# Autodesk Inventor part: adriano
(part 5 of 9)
sketch "スケッチ139"
  geometry: L1 (17.25, -13.45)-(17.25, -5.9) reference; L2 (4.25, -13.4)-(4.25, -5.9) reference; L3 (4.25, -5.9)-(8.25, -5.9) reference; L4 (8.25, -5.9)-(8.25, -13.4) reference; L5 (8.25, -13.4)-(4.25, -13.4) reference; L6 (10.75, -13.45)-(10.75, -5.9) reference; L7 (23.75, -13.45)-(23.75, -5.9) reference; L8 (31.5, -17.464)-(31.5, -1.6) reference; L9 (4.25, -6.4)-(3.75, -6.4); L10 (3.75, -6.4)-(3.75, -5.4); L11 (3.75, -5.4)-(8.75, -5.4); L12 (8.75, -5.4)-(8.75, -6.4); L13 (8.75, -6.4)-(8.25, -6.4); L14 (8.25, -6.4)-(8.25, -5.9); L15 (8.25, -5.9)-(4.25, -5.9); L16 (4.25, -5.9)-(4.25, -6.4); L17 (15.25, -5.4)-(15.25, -6.4); L18 (14.75, -6.4)-(14.75, -5.9); L19 (15.25, -6.4)-(14.75, -6.4); L20 (10.75, -5.9)-(10.75, -6.4); L21 (10.75, -5.9)-(14.75, -5.9); L22 (14.75, -5.9)-(10.75, -5.9); L23 (10.75, -6.4)-(10.25, -6.4); L24 (10.25, -6.4)-(10.25, -5.4); L25 (10.25, -5.4)-(15.25, -5.4); L26 (17.25, -5.9)-(17.25, -6.4); L27 (16.75, -6.4)-(16.75, -5.4); L28 (21.75, -6.4)-(21.25, -6.4); L29 (21.25, -6.4)-(21.25, -5.9); L30 (21.25, -5.9)-(17.25, -5.9); L31 (16.75, -5.4)-(21.75, -5.4); L32 (21.75, -5.4)-(21.75, -6.4); L33 (17.25, -6.4)-(16.75, -6.4); L34 (17.25, -5.9)-(21.25, -5.9); L35 (23.75, -6.4)-(23.25, -6.4); L36 (23.75, -5.9)-(23.75, -6.4); L37 (23.25, -6.4)-(23.25, -5.4); L38 (23.75, -5.9)-(27.75, -5.9); L39 (28.25, -6.4)-(27.75, -6.4); L40 (23.25, -5.4)-(28.25, -5.4); L41 (28.25, -5.4)-(28.25, -6.4); L42 (27.75, -6.4)-(27.75, -5.9); L43 (27.75, -5.9)-(23.75, -5.9); L44 (3.75, -10.9)-(8.75, -10.9); L45 (8.75, -10.9)-(8.75, -13.9); L46 (8.75, -13.9)-(3.75, -13.9); L47 (3.75, -13.9)-(3.75, -10.9); L48 (10.25, -10.9)-(15.25, -10.9); L49 (15.25, -10.9)-(15.25, -13.9); L50 (15.25, -13.9)-(10.25, -13.9); L51 (10.25, -13.9)-(10.25, -10.9); L52 (16.75, -10.9)-(21.75, -10.9); L53 (21.75, -10.9)-(21.75, -13.9); L54 (21.75, -13.9)-(16.75, -13.9); L55 (16.75, -13.9)-(16.75, -10.9); L56 (23.25, -10.9)-(28.25, -10.9); L57 (28.25, -10.9)-(28.25, -13.9); L58 (28.25, -13.9)-(23.25, -13.9); L59 (23.25, -13.9)-(23.25, -10.9); L60 (3.75, -28.5)-(8.75, -28.5); L61 (8.75, -28.5)-(8.75, -31.5); L62 (8.75, -31.5)-(3.75, -31.5); L63 (3.75, -31.5)-(3.75, -28.5); L64 (10.25, -28.5)-(15.25, -28.5)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; A1 r 2.499 centre (6.25, -23.5) between (8.749, -23.5) and (3.751, -23.5); A2 r 1.999 centre (6.25, -23.5) between (8.249, -23.5) and (4.251, -23.5); A3 r 2.49 centre (12.75, -23.5) between (15.24, -23.5) and (10.26, -23.5); A4 r 1.99 centre (12.75, -23.5) between (14.74, -23.5) and (10.76, -23.5); A5 r 2.492 centre (19.25, -23.5) between (21.742, -23.5) and (16.758, -23.5); A6 r 1.992 centre (19.25, -23.5) between (21.242, -23.5) and (17.258, -23.5); A7 r 2.5 centre (25.75, -23.5) between (28.25, -23.5) and (23.25, -23.5); A8 r 2 centre (25.75, -23.5) between (27.75, -23.5) and (23.75, -23.5); 1 further point
  constraints: 150 end point, 25 parallel, 19 perpendicular, 16 point on circle, 8 centre point, 8 horizontal, 7 collinear, 4 coincident, 2 point on line
  dimensions: "d2453" = 0.5 distance of L9.start L9.end; "d2455" = 0.5 distance of L12.end L13.end; "d2456" = 0.5 distance between parallel lines of L11 L3; "d2457" = 1 distance of L9.end L10.end; "d2458" = 0 distance from line of L13.end L9; "d2459" = 0.5 distance of L20.end L23.end; "d2460" = 0.5 distance of L17.end L18.start; "d2461" = 0.5 distance between parallel lines of L25 L21; "d2462" = 1 distance of L23.end L24.end; "d2463" = 0 distance from line of L18.start L23; "d2464" = 0.5 distance of L26.end L27.start; "d2465" = 0.5 distance of L28.start L28.end; "d2466" = 0.5 distance between parallel lines of L31 L34; "d2467" = 1 distance of L27.start L27.end; "d2468" = 0 distance from line of L28.end L33; "d2469" = 0.5 distance of L35.start L35.end; "d2470" = 0.5 distance of L39.start L39.end; "d2471" = 0.5 distance between parallel lines of L40 L38; "d2472" = 1 distance of L35.end L37.end; "d2473" = 0 distance from line of L39.end L35; "d2474" = 0 distance between parallel lines of L25 L11; "d2475" = 0 distance between parallel lines of L31 L25; "d2476" = 0 distance between parallel lines of L40 L31; "d2477" = 0 distance between parallel lines of L6 L20; "d2478" = 0 distance between parallel lines of L1 L26; "d2479" = 0 distance between parallel lines of L7 L36; "d2480" = 0.5 distance between parallel lines of L5 L46; "d2481" = 0 distance between parallel lines of L50 L46; "d2482" = 0 distance between parallel lines of L54 L50; "d2483" = 0 distance between parallel lines of L58 L54; "d2484" = 0 distance between parallel lines of L52 L56; "d2485" = 3 distance of L46.end L44.start; "d2486" = 0 distance between parallel lines of L48 L44; "d2487" = 0 distance between parallel lines of L52 L48; "d2488" = 3 distance of L62.end L60.start; "d2489" = 0 distance between parallel lines of L64 L60; "d2490" = 0 distance between parallel lines of L68 L64; "d2491" = 0 distance between parallel lines of L72 L68; "d2492" = 0 distance between parallel lines of L66 L62; "d2493" = 0 distance between parallel lines of L70 L66; "d2494" = 0 distance between parallel lines of L74 L70; "d2495" = 0.5 distance between parallel lines of L62 L76; "d2496" = 0.5 distance of L77.start L77.end; "d2497" = 0.5 distance of L79.start L79.end; "d2498" = 0.5 distance of L82.start L82.end; "d2499" = 0.5 distance of L83.start L83.end; "d2500" = 0 vertical distance of A3.centre A1.centre; "d2501" = 0 vertical distance of A5.centre A3.centre; "d2502" = 0 vertical distance of A7.centre A5.centre; "d2503" = 0 vertical distance of L80.end L81.start; "d2504" = 0 distance between parallel lines of L79 L80; "d2505" = 0 distance from line of A3.centre L79; "d2506" = 0 distance between parallel lines of L79 L78; "d2507" = 5 distance from line of L60 A1.centre; "d2508" = 0 distance between parallel lines of L82 L77; "d2509" = 0 distance between parallel lines of L78 L77
extrude "押し出し129" join sketch "スケッチ139" distance "d2510" = 0.5; taper "d2511" = 0 deg
sketch "スケッチ141"
  geometry: L1 (-14.75, 20.4)-(-14.75, 27.9) reference; L2 (-14.75, 27.9)-(-10.75, 27.9) reference; L3 (-21.25, 20.4)-(-21.25, 27.9) reference; L4 (-21.25, 27.9)-(-17.25, 27.9) reference; L5 (-17.25, 27.9)-(-17.25, 20.4) reference; L6 (-8.25, 20.4)-(-8.25, 27.9) reference; L7 (-8.25, 27.9)-(-4.25, 27.9) reference; L8 (-0.5, 16.536)-(-25.5, 16.536) reference; L9 (-21.25, 27.4)-(-21.75, 27.4); L10 (-21.75, 27.4)-(-21.75, 28.4); L11 (-21.75, 28.4)-(-16.75, 28.4); L12 (-16.75, 28.4)-(-16.75, 27.4); L13 (-16.75, 27.4)-(-17.25, 27.4); L14 (-17.25, 27.4)-(-17.25, 27.9); L15 (-17.25, 27.9)-(-21.25, 27.9); L16 (-21.25, 27.9)-(-21.25, 27.4); L17 (-15.25, 27.4)-(-15.25, 28.4); L18 (-14.75, 27.4)-(-15.25, 27.4); L19 (-14.75, 27.9)-(-14.75, 27.4); L20 (-10.25, 27.4)-(-10.75, 27.4); L21 (-10.75, 27.4)-(-10.75, 27.9); L22 (-14.75, 27.9)-(-10.75, 27.9); L23 (-10.25, 28.4)-(-10.25, 27.4); L24 (-15.25, 28.4)-(-10.25, 28.4); L25 (-10.75, 27.9)-(-14.75, 27.9); L26 (-8.25, 27.4)-(-8.75, 27.4); L27 (-3.75, 27.4)-(-4.25, 27.4); L28 (-8.25, 27.9)-(-8.25, 27.4); L29 (-4.25, 27.4)-(-4.25, 27.9); L30 (-4.25, 27.9)-(-8.25, 27.9); L31 (-8.75, 27.4)-(-8.75, 28.4); L32 (-8.75, 28.4)-(-3.75, 28.4); L33 (-3.75, 28.4)-(-3.75, 27.4); L34 (-8.25, 27.9)-(-4.25, 27.9); L35 (-21.75, 23.001)-(-16.75, 23.001); L36 (-16.75, 23.001)-(-16.75, 20.001); L37 (-16.75, 20.001)-(-21.75, 20.001); L38 (-21.75, 20.001)-(-21.75, 23.001); L39 (-15.25, 23.001)-(-10.25, 23.001); L40 (-10.25, 23.001)-(-10.25, 20.001); L41 (-10.25, 20.001)-(-15.25, 20.001); L42 (-15.25, 20.001)-(-15.25, 23.001); L43 (-8.75, 23.001)-(-3.75, 23.001); L44 (-3.75, 23.001)-(-3.75, 20.001); L45 (-3.75, 20.001)-(-8.75, 20.001); L46 (-8.75, 20.001)-(-8.75, 23.001); L47 (-21.75, 5.5)-(-16.75, 5.5); L48 (-16.75, 5.5)-(-16.75, 2.5); L49 (-16.75, 2.5)-(-21.75, 2.5); L50 (-21.75, 2.5)-(-21.75, 5.5); L51 (-15.25, 5.5)-(-10.25, 5.5); L52 (-10.25, 5.5)-(-10.25, 2.5); L53 (-10.25, 2.5)-(-15.25, 2.5); L54 (-15.25, 2.5)-(-15.25, 5.5); L55 (-8.75, 5.5)-(-3.75, 5.5); L56 (-3.75, 5.5)-(-3.75, 2.5); L57 (-3.75, 2.5)-(-8.75, 2.5); L58 (-8.75, 2.5)-(-8.75, 5.5); L59 (-17.25, 3)-(-21.25, 3) reference; L60 (-14.75, 3)-(-14.75, 10.5) reference; L61 (-8.25, 3)-(-8.25, 10.5) reference; L62 (-21.75, 10.5)-(-21.25, 10.5); L63 (-17.25, 10.5)-(-16.75, 10.5); L64 (-15.25, 10.5)-(-14.75, 10.5)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; A1 r 2.5 centre (-19.25, 10.5) between (-16.75, 10.5) and (-21.75, 10.5); A2 r 2 centre (-19.25, 10.5) between (-17.25, 10.5) and (-21.25, 10.5); A3 r 2.5 centre (-12.75, 10.5) between (-10.25, 10.5) and (-15.25, 10.5); A4 r 2 centre (-12.75, 10.5) between (-10.75, 10.5) and (-14.75, 10.5); A5 r 2.5 centre (-6.25, 10.5) between (-3.75, 10.5) and (-8.75, 10.5); A6 r 2 centre (-6.25, 10.5) between (-4.25, 10.5) and (-8.25, 10.5); 2 further points
  constraints: 112 end point, 19 parallel, 14 perpendicular, 12 point on circle, 7 collinear, 6 centre point, 6 horizontal, 3 coincident, 2 point on line
  dimensions: "d2544" = 0.5 distance of L9.start L9.end; "d2546" = 0.5 distance of L12.end L13.end; "d2547" = 0.5 distance between parallel lines of L4 L11; "d2548" = 1 distance of L9.end L10.end; "d2549" = 0 distance between parallel lines of L13 L9; "d2550" = 0.5 distance of L18.start L17.start; "d2551" = 0.5 distance of L20.start L20.end; "d2552" = 0.5 distance between parallel lines of L22 L24; "d2553" = 1 distance of L17.start L17.end; "d2554" = 0 distance between parallel lines of L20 L18; "d2555" = 0.5 distance of L26.start L26.end; "d2556" = 0.5 distance of L27.start L27.end; "d2557" = 0.5 distance between parallel lines of L34 L32; "d2558" = 1 distance of L26.end L31.end; "d2559" = 0 distance between parallel lines of L27 L26; "d2560" = 0 distance between parallel lines of L1 L19; "d2561" = 0 distance between parallel lines of L2 L22; "d2562" = 0 distance between parallel lines of L6 L28; "d2563" = 0 distance between parallel lines of L30 L7; "d2564" = 3 distance of L37.end L35.start; "d2565" = 0 distance between parallel lines of L39 L35; "d2566" = 0 distance between parallel lines of L43 L39; "d2567" = 0 distance between parallel lines of L41 L37; "d2568" = 0 distance between parallel lines of L45 L41; "d2569" = 3 distance of L49.end L47.start; "d2570" = 0.5 distance between parallel lines of L59 L49; "d2571" = 0 distance between parallel lines of L51 L47; "d2572" = 0 distance between parallel lines of L53 L49; "d2573" = 0 distance between parallel lines of L55 L51; "d2574" = 0 distance between parallel lines of L57 L53; "d2575" = 0.5 distance between parallel lines of L60 L54; "d2576" = 0.5 distance between parallel lines of L61 L58; "d2577" = 5 distance of L56.end L57.end; "d2578" = 5 distance of L52.end L53.end; "d2579" = 0.5 distance of L62.start L62.end; "d2580" = 0.5 distance of L64.start L60.end; "d2580" = 0.5 distance of L64.start L60.end; "d2581" = 0.5 distance of L66.start L61.end
extrude "押し出し131" join sketch "スケッチ141" distance "d2582" = 0.5; taper "d2583" = 0 deg
sketch "スケッチ142"
  geometry: L1 (4, 4.6)-(4, 12.036) reference; L2 (4, 12.036)-(8, 12.036) reference; L3 (8, 12.036)-(8, 4.6) reference; L4 (17, 4.536)-(17, 12.036) reference; L5 (17, 12.036)-(21, 12.036) reference; L6 (21, 12.036)-(21, 4.536) reference; L7 (10.5, 4.6)-(10.5, 12.036) reference; L8 (10.5, 12.036)-(14.5, 12.036) reference; L9 (14.5, 12.036)-(14.5, 4.6) reference; L10 (4, 11.536)-(3.5, 11.536); L11 (3.5, 11.536)-(3.5, 12.536); L12 (3.5, 12.536)-(8.5, 12.536); L13 (8.5, 12.536)-(8.5, 11.536); L14 (8.5, 11.536)-(8, 11.536); L15 (8, 11.536)-(8, 12.036); L16 (8, 12.036)-(4, 12.036); L17 (4, 12.036)-(4, 11.536); L18 (10.5, 11.536)-(10, 11.536); L19 (10, 11.536)-(10, 12.536); L20 (10, 12.536)-(15, 12.536); L21 (15, 12.536)-(15, 11.536); L22 (15, 11.536)-(14.5, 11.536); L23 (14.5, 11.536)-(14.5, 12.036); L24 (14.5, 12.036)-(10.5, 12.036); L25 (10.5, 12.036)-(10.5, 11.536); L26 (17, 11.536)-(16.5, 11.536); L27 (16.5, 11.536)-(16.5, 12.536); L28 (17, 12.036)-(21, 12.036); L29 (21, 12.036)-(17, 12.036); L30 (16.5, 12.536)-(21.5, 12.536); L31 (17, 12.036)-(17, 11.536); L32 (21, 11.536)-(21, 12.036); L33 (21.5, 11.536)-(21, 11.536); L34 (21.5, 12.536)-(21.5, 11.536); L35 (3.5, 7.154)-(8.5, 7.154); L36 (8.5, 7.154)-(8.5, 4.154); L37 (8.5, 4.154)-(3.5, 4.154); L38 (3.5, 4.154)-(3.5, 7.154); L39 (10, 7.154)-(15, 7.154); L40 (15, 7.154)-(15, 4.154); L41 (15, 4.154)-(10, 4.154); L42 (10, 4.154)-(10, 7.154); L43 (16.5, 7.154)-(21.5, 7.154); L44 (21.5, 7.154)-(21.5, 4.154); L45 (21.5, 4.154)-(16.5, 4.154); L46 (16.5, 4.154)-(16.5, 7.154); 1 further point
  constraints: 74 end point, 12 parallel, 12 perpendicular, 4 collinear, 4 point on line, 3 horizontal
  dimensions: "d2584" = 0.5 distance of L10.start L10.end; "d2586" = 0.5 distance of L13.end L14.end; "d2587" = 0.5 distance between parallel lines of L12 L2; "d2588" = 1 distance of L10.end L11.end; "d2589" = 0 distance between parallel lines of L14 L10; "d2590" = 0.5 distance of L18.start L18.end; "d2591" = 0.5 distance of L21.end L22.end; "d2592" = 0.5 distance between parallel lines of L8 L20; "d2593" = 1 distance of L18.end L19.end; "d2594" = 0.5 distance of L26.start L26.end; "d2595" = 0.5 distance of L33.start L32.start; "d2596" = 0.5 distance between parallel lines of L28 L30; "d2597" = 1 distance of L26.end L27.end; "d2598" = 0 distance between parallel lines of L5 L28; "d2599" = 0 distance between parallel lines of L6 L32; "d2600" = 0 distance between parallel lines of L4 L31; "d2601" = 3 distance of L37.end L35.start; "d2602" = 0 distance between parallel lines of L39 L35; "d2603" = 0 distance between parallel lines of L43 L39; "d2604" = 0 distance between parallel lines of L41 L37; "d2605" = 0 distance between parallel lines of L45 L41
extrude "押し出し132" join sketch "スケッチ142" distance "d2606" = 0.5; taper "d2607" = 0 deg
sketch "スケッチ143"
  geometry: L1 (16.25, -13.45)-(16.25, -5.95) reference; L2 (16.25, -5.95)-(20.25, -5.95) reference; L3 (20.25, -5.95)-(20.25, -13.45) reference; L4 (3.25, -13.45)-(3.25, -5.95) reference; L5 (3.25, -5.95)-(7.25, -5.95) reference; L6 (7.25, -5.95)-(7.25, -13.45) reference; L7 (9.75, -13.45)-(9.75, -5.95) reference; L8 (9.75, -5.95)-(13.75, -5.95) reference; L9 (22.75, -13.45)-(22.75, -5.95) reference; L10 (22.75, -5.95)-(26.75, -5.95) reference; L11 (26.75, -5.95)-(26.75, -13.45) reference; L12 (30.5, -17.464)-(-0.5, -17.464) reference; L13 (3.25, -6.45)-(2.75, -6.45); L14 (2.75, -6.45)-(2.75, -5.45); L15 (2.75, -5.45)-(7.75, -5.45); L16 (7.75, -5.45)-(7.75, -6.45); L17 (7.75, -6.45)-(7.25, -6.45); L18 (7.25, -6.45)-(7.25, -5.95); L19 (7.25, -5.95)-(3.25, -5.95); L20 (3.25, -5.95)-(3.25, -6.45); L21 (14.25, -6.45)-(13.75, -6.45); L22 (13.75, -6.45)-(13.75, -5.95); L23 (14.25, -5.45)-(14.25, -6.45); L24 (9.75, -5.95)-(13.75, -5.95); L25 (13.75, -5.95)-(9.75, -5.95); L26 (9.25, -5.45)-(14.25, -5.45); L27 (9.75, -5.95)-(9.75, -6.45); L28 (9.75, -6.45)-(9.25, -6.45); L29 (9.25, -6.45)-(9.25, -5.45); L30 (20.75, -5.45)-(20.75, -6.45); L31 (20.75, -6.45)-(20.25, -6.45); L32 (20.25, -5.95)-(16.25, -5.95); L33 (16.25, -6.45)-(15.75, -6.45); L34 (15.75, -5.45)-(20.75, -5.45); L35 (16.25, -5.95)-(20.25, -5.95); L36 (15.75, -6.45)-(15.75, -5.45); L37 (16.25, -5.95)-(16.25, -6.45); L38 (20.25, -6.45)-(20.25, -5.95); L39 (22.75, -6.45)-(22.25, -6.45); L40 (22.75, -5.95)-(22.75, -6.45); L41 (22.25, -6.45)-(22.25, -5.45); L42 (22.75, -5.95)-(26.75, -5.95); L43 (22.25, -5.45)-(27.25, -5.45); L44 (27.25, -6.45)-(26.75, -6.45); L45 (26.75, -6.45)-(26.75, -5.95); L46 (27.25, -5.45)-(27.25, -6.45); L47 (26.75, -5.95)-(22.75, -5.95); L48 (2.75, -11.178)-(7.75, -11.178); L49 (7.75, -11.178)-(7.75, -14.178); L50 (7.75, -14.178)-(2.75, -14.178); L51 (2.75, -14.178)-(2.75, -11.178); L52 (9.25, -11.178)-(14.25, -11.178); L53 (14.25, -11.178)-(14.25, -14.178); L54 (14.25, -14.178)-(9.25, -14.178); L55 (9.25, -14.178)-(9.25, -11.178); L56 (15.75, -11.178)-(20.75, -11.178); L57 (20.75, -11.178)-(20.75, -14.178); L58 (20.75, -14.178)-(15.75, -14.178); L59 (15.75, -14.178)-(15.75, -11.178); L60 (22.25, -11.178)-(27.25, -11.178); L61 (27.25, -11.178)-(27.25, -14.178); L62 (27.25, -14.178)-(22.25, -14.178); L63 (22.25, -14.178)-(22.25, -11.178); L64 (2.75, -28.5)-(7.66, -28.5)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; A1 r 2.426 centre (5.236, -23.5) between (7.66, -23.382) and (2.81, -23.5); A2 r 1.926 centre (5.236, -23.5) between (7.159, -23.382) and (3.31, -23.5); A3 r 2.003 centre (11.75, -23.5) between (13.75, -23.399) and (9.75, -23.382); A4 r 2.502 centre (11.75, -23.5) between (14.25, -23.399) and (9.25, -23.382); A5 r 2.501 centre (18.249, -23.5) between (20.75, -23.5) and (15.75, -23.399); A6 r 2.002 centre (18.249, -23.5) between (20.251, -23.5) and (16.25, -23.399); A7 r 2.416 centre (24.734, -23.5) between (27.15, -23.5) and (22.318, -23.5); A8 r 1.916 centre (24.734, -23.5) between (26.65, -23.5) and (22.818, -23.5); 2 further points
  constraints: 150 end point, 29 parallel, 16 point on circle, 13 perpendicular, 10 collinear, 8 centre point, 8 horizontal, 4 coincident, 2 point on line
  dimensions: "d2608" = 0.5 distance of L13.start L13.end; "d2610" = 0.5 distance of L16.end L17.end; "d2611" = 0.5 distance between parallel lines of L15 L5; "d2612" = 1 distance of L13.end L14.end; "d2613" = 0 distance between parallel lines of L17 L13; "d2614" = 0.5 distance of L27.end L28.end; "d2615" = 0.5 distance of L21.start L21.end; "d2616" = 0.5 distance between parallel lines of L26 L24; "d2617" = 1 distance of L28.end L26.start; "d2618" = 0 distance between parallel lines of L21 L28; "d2619" = 0 distance between parallel lines of L8 L24; "d2620" = 0 distance from line of L7 L27.end; "d2621" = 0.5 distance of L33.start L33.end; "d2622" = 0.5 distance of L30.end L31.end; "d2623" = 0.5 distance between parallel lines of L34 L35; "d2624" = 1 distance of L33.end L34.start; "d2625" = 0 distance between parallel lines of L31 L33; "d2626" = 0.5 distance of L39.start L39.end; "d2627" = 0.5 distance of L44.start L44.end; "d2628" = 0.5 distance between parallel lines of L43 L42; "d2629" = 1 distance of L39.end L41.end; "d2630" = 0 distance between parallel lines of L44 L39; "d2631" = 0 distance between parallel lines of L2 L32; "d2632" = 0 distance between parallel lines of L1 L37; "d2633" = 0 distance between parallel lines of L42 L10; "d2634" = 0 distance from line of L11 L44.end; "d2635" = 0 distance between parallel lines of L9 L40; "d2636" = 3 distance of L50.end L48.start; "d2637" = 0 distance between parallel lines of L52 L48; "d2638" = 0 distance between parallel lines of L56 L52; "d2639" = 0 distance between parallel lines of L60 L56; "d2640" = 0 distance between parallel lines of L54 L50; "d2641" = 0 distance between parallel lines of L58 L54; "d2642" = 0 distance between parallel lines of L62 L58; "d2643" = 5 distance of L49.end L50.end; "d2644" = 5 distance of L53.end L54.end; "d2645" = 5 distance of L57.end L58.end; "d2646" = 5 distance of L61.end L62.end; "d2647" = 3 distance of L66.end L64.start; "d2648" = 0 distance between parallel lines of L68 L64; "d2649" = 0 distance between parallel lines of L72 L68; "d2650" = 0 distance between parallel lines of L76 L72; "d2651" = 0 distance between parallel lines of L70 L66; "d2652" = 0 distance between parallel lines of L74 L70; "d2653" = 0 distance between parallel lines of L78 L74; "d2654" = 0.5 distance between parallel lines of L80 L66; "d2655" = 0.5 distance of L81.start L81.end; "d2656" = 0.5 distance of L83.start L83.end; "d2657" = 0.5 distance of L85.start L85.end; "d2658" = 0.5 distance of L87.start L87.end; "d2659" = 5 distance between parallel lines of L64 L81; "d2660" = 0 distance between parallel lines of L83 L82; "d2661" = 0 distance between parallel lines of L85 L84; "d2662" = 0 distance from line of L65 L82.end; "d2663" = 0 distance from line of L69 L84.end; "d2664" = 0 distance from line of L73 L86.end; "d2665" = 0 distance between parallel lines of L73 L57; "d2666" = 0 distance between parallel lines of L57 L30; "d2667" = 0 distance between parallel lines of L3 L38; "d2668" = 0 distance from line of L83.start L71; "d2669" = 0 distance between parallel lines of L71 L55; "d2670" = 0 distance between parallel lines of L55 L29; "d2671" = 0 distance from line of L85.start L75; "d2672" = 0 distance between parallel lines of L59 L75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
extrude "押し出し133" join sketch "スケッチ143" distance "d2681" = 0.5; taper "d2682" = 0 deg
sketch "スケッチ144"
  geometry: L1 (8.5, 7.154)-(3.5, 7.154) reference; L2 (3.5, 7.154)-(3.5, 4.154) reference; L3 (3.5, 4.154)-(8.5, 4.154) reference; L4 (4.05, 6.654)-(4.65, 6.654); L5 (4.65, 6.654)-(4.65, 4.954); L6 (4.65, 4.954)-(4.05, 4.954); L7 (4.05, 4.954)-(4.05, 6.654); L8 (5.15, 6.654)-(5.75, 6.654); L9 (5.75, 6.654)-(5.75, 4.954); L10 (5.75, 4.954)-(5.15, 4.954); L11 (5.15, 4.954)-(5.15, 6.654); L12 (6.25, 6.654)-(6.85, 6.654); L13 (6.85, 6.654)-(6.85, 4.954); L14 (6.85, 4.954)-(6.25, 4.954); L15 (6.25, 4.954)-(6.25, 6.654); L16 (7.35, 6.654)-(7.95, 6.654); L17 (7.95, 6.654)-(7.95, 4.954); L18 (7.95, 4.954)-(7.35, 4.954); L19 (7.35, 4.954)-(7.35, 6.654); L20 (10.55, 6.654)-(11.15, 6.654); L21 (11.15, 6.654)-(11.15, 4.954); L22 (11.15, 4.954)-(10.55, 4.954); L23 (10.55, 4.954)-(10.55, 6.654); L24 (11.65, 6.654)-(12.25, 6.654); L25 (12.25, 6.654)-(12.25, 4.954); L26 (12.25, 4.954)-(11.65, 4.954); L27 (11.65, 4.954)-(11.65, 6.654); L28 (12.75, 6.654)-(13.35, 6.654); L29 (13.35, 6.654)-(13.35, 4.954); L30 (13.35, 4.954)-(12.75, 4.954); L31 (12.75, 4.954)-(12.75, 6.654); L32 (13.85, 6.654)-(14.45, 6.654); L33 (14.45, 6.654)-(14.45, 4.954); L34 (14.45, 4.954)-(13.85, 4.954); L35 (13.85, 4.954)-(13.85, 6.654); L36 (10, 7.154)-(10, 4.154) reference; L37 (10, 4.154)-(15, 4.154) reference; L38 (17.05, 6.654)-(17.65, 6.654); L39 (17.65, 6.654)-(17.65, 4.954); L40 (17.65, 4.954)-(17.05, 4.954); L41 (17.05, 4.954)-(17.05, 6.654); L42 (18.15, 6.654)-(18.75, 6.654); L43 (18.75, 6.654)-(18.75, 4.954); L44 (18.75, 4.954)-(18.15, 4.954); L45 (18.15, 4.954)-(18.15, 6.654); L46 (19.25, 6.654)-(19.85, 6.654); L47 (19.85, 6.654)-(19.85, 4.954); L48 (19.85, 4.954)-(19.25, 4.954); L49 (19.25, 4.954)-(19.25, 6.654); L50 (20.35, 6.654)-(20.95, 6.654); L51 (20.95, 6.654)-(20.95, 4.954); L52 (20.95, 4.954)-(20.35, 4.954); L53 (20.35, 4.954)-(20.35, 6.654); L54 (16.5, 7.154)-(16.5, 4.154) reference; 1 further point
  constraints: 96 end point, 24 parallel, 12 horizontal, 12 perpendicular
  dimensions: "d2683" = 0.6 distance of L4.start L4.end; "d2685" = 0.6 distance of L8.start L8.end; "d2686" = 0.6 distance of L12.start L12.end; "d2687" = 0.6 distance of L16.start L16.end; "d2688" = 0.5 distance between parallel lines of L11 L5; "d2689" = 0.5 distance between parallel lines of L15 L9; "d2690" = 0.5 distance between parallel lines of L13 L19; "d2691" = 0.55 distance between parallel lines of L7 L2; "d2692" = 0.8 distance between parallel lines of L3 L6; "d2693" = 0 distance between parallel lines of L10 L6; "d2694" = 0 distance between parallel lines of L14 L10; "d2695" = 0 distance between parallel lines of L18 L14; "d2696" = 0.5 distance between parallel lines of L4 L1; "d2697" = 0.5 distance between parallel lines of L27 L21; "d2698" = 0.5 distance between parallel lines of L31 L25; "d2699" = 0.5 distance between parallel lines of L35 L29; "d2700" = 0.55 distance between parallel lines of L36 L23; "d2701" = 0.6 distance of L20.start L20.end; "d2702" = 0.6 distance of L24.start L24.end; "d2703" = 0.6 distance of L28.start L28.end; "d2704" = 0.6 distance of L32.start L32.end; "d2705" = 0.8 distance between parallel lines of L37 L22; "d2706" = 0.55 distance between parallel lines of L54 L41; "d2707" = 0.6 distance of L38.start L38.end; "d2708" = 0.5 distance between parallel lines of L45 L39; "d2709" = 0.6 distance of L42.start L42.end; "d2710" = 0.5 distance between parallel lines of L49 L43; "d2711" = 0.6 distance of L46.start L46.end; "d2712" = 0.5 distance between parallel lines of L53 L47; "d2713" = 0.6 distance of L50.start L50.end
extrude "押し出し134" cut sketch "スケッチ144" distance "d2714" = 0.5; taper "d2715" = 0 deg
sketch "スケッチ146"
  geometry: L1 (-16.75, 23.001)-(-21.75, 23.001) reference; L2 (-21.75, 23.001)-(-21.75, 20.001) reference; L3 (-21.75, 20.001)-(-16.75, 20.001) reference; L4 (-21.2, 22.501)-(-20.6, 22.501); L5 (-20.6, 22.501)-(-20.6, 20.801); L6 (-20.6, 20.801)-(-21.2, 20.801); L7 (-21.2, 20.801)-(-21.2, 22.501); L8 (-20.1, 22.501)-(-19.5, 22.501); L9 (-19.5, 22.501)-(-19.5, 20.801); L10 (-19.5, 20.801)-(-20.1, 20.801); L11 (-20.1, 20.801)-(-20.1, 22.501); L12 (-19, 22.501)-(-18.4, 22.501); L13 (-18.4, 22.501)-(-18.4, 20.801); L14 (-18.4, 20.801)-(-19, 20.801); L15 (-19, 20.801)-(-19, 22.501); L16 (-17.9, 22.501)-(-17.3, 22.501); L17 (-17.3, 22.501)-(-17.3, 20.801); L18 (-17.3, 20.801)-(-17.9, 20.801); L19 (-17.9, 20.801)-(-17.9, 22.501); L20 (-14.7, 22.501)-(-14.1, 22.501); L21 (-14.1, 22.501)-(-14.1, 20.801); L22 (-14.1, 20.801)-(-14.7, 20.801); L23 (-14.7, 20.801)-(-14.7, 22.501); L24 (-13.6, 22.501)-(-13, 22.501); L25 (-13, 22.501)-(-13, 20.801); L26 (-13, 20.801)-(-13.6, 20.801); L27 (-13.6, 20.801)-(-13.6, 22.501); L28 (-12.5, 22.501)-(-11.9, 22.501); L29 (-11.9, 22.501)-(-11.9, 20.801); L30 (-11.9, 20.801)-(-12.5, 20.801); L31 (-12.5, 20.801)-(-12.5, 22.501); L32 (-11.4, 22.501)-(-10.8, 22.501); L33 (-10.8, 22.501)-(-10.8, 20.801); L34 (-10.8, 20.801)-(-11.4, 20.801); L35 (-11.4, 20.801)-(-11.4, 22.501); L36 (-15.25, 23.001)-(-15.25, 20.001) reference; L37 (-8.2, 22.501)-(-7.6, 22.501); L38 (-7.6, 22.501)-(-7.6, 20.801); L39 (-7.6, 20.801)-(-8.2, 20.801); L40 (-8.2, 20.801)-(-8.2, 22.501); L41 (-7.1, 22.501)-(-6.5, 22.501); L42 (-6.5, 22.501)-(-6.5, 20.801); L43 (-6.5, 20.801)-(-7.1, 20.801); L44 (-7.1, 20.801)-(-7.1, 22.501); L45 (-6, 22.501)-(-5.4, 22.501); L46 (-5.4, 22.501)-(-5.4, 20.801); L47 (-5.4, 20.801)-(-6, 20.801); L48 (-6, 20.801)-(-6, 22.501); L49 (-4.9, 22.501)-(-4.3, 22.501); L50 (-4.3, 22.501)-(-4.3, 20.801); L51 (-4.3, 20.801)-(-4.9, 20.801); L52 (-4.9, 20.801)-(-4.9, 22.501); L53 (-8.75, 23.001)-(-8.75, 20.001) reference; L54 (-21.2, 5)-(-20.6, 5); L55 (-20.6, 5)-(-20.6, 3.3); L56 (-20.6, 3.3)-(-21.2, 3.3); L57 (-21.2, 3.3)-(-21.2, 5); L58 (-20.1, 5)-(-19.5, 5); L59 (-19.5, 5)-(-19.5, 3.3); L60 (-19.5, 3.3)-(-20.1, 3.3); L61 (-20.1, 3.3)-(-20.1, 5); L62 (-19, 5)-(-18.4, 5); L63 (-18.4, 5)-(-18.4, 3.3); L64 (-18.4, 3.3)-(-19, 3.3)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; 1 further point
  constraints: 192 end point, 48 parallel, 24 horizontal, 24 perpendicular
  dimensions: "d2747" = 0.6 distance of L4.start L4.end; "d2749" = 0.55 distance between parallel lines of L2 L7; "d2750" = 0.5 distance between parallel lines of L11 L5; "d2751" = 0.5 distance between parallel lines of L15 L9; "d2752" = 0.5 distance between parallel lines of L19 L13; "d2753" = 0.6 distance of L8.start L8.end; "d2754" = 0.6 distance of L12.start L12.end; "d2755" = 0.6 distance of L16.start L16.end; "d2756" = 0.8 distance between parallel lines of L3 L6; "d2757" = 0 distance between parallel lines of L10 L6; "d2758" = 0 distance between parallel lines of L14 L10; "d2759" = 0 distance from line of L18.end L14; "d2760" = 0.5 distance between parallel lines of L4 L1; "d2761" = 0.55 distance between parallel lines of L36 L23; "d2762" = 0.5 distance between parallel lines of L27 L21; "d2763" = 0.5 distance between parallel lines of L31 L25; "d2764" = 0.5 distance between parallel lines of L35 L29; "d2765" = 0.6 distance of L20.start L20.end; "d2766" = 0.6 distance of L24.start L24.end; "d2767" = 0.6 distance of L28.start L28.end; "d2768" = 0.6 distance of L32.start L32.end; "d2769" = 0.55 distance between parallel lines of L40 L53; "d2770" = 0.5 distance between parallel lines of L44 L38; "d2771" = 0.5 distance between parallel lines of L48 L42; "d2772" = 0.5 distance between parallel lines of L46 L52; "d2773" = 0.6 distance of L37.start L37.end; "d2774" = 0.6 distance of L41.start L41.end; "d2775" = 0.6 distance of L45.start L45.end; "d2776" = 0.6 distance of L49.start L49.end; "d2777" = 0.5 distance between parallel lines of L54 L70; "d2778" = 0.8 distance between parallel lines of L71 L56; "d2779" = 0 distance between parallel lines of L60 L56; "d2780" = 0 distance between parallel lines of L64 L60; "d2781" = 0 distance between parallel lines of L68 L64; "d2782" = 0 distance between parallel lines of L58 L54; "d2783" = 0 distance between parallel lines of L62 L58; "d2784" = 0 distance between parallel lines of L66 L62
extrude "押し出し136" cut sketch "スケッチ146" distance "d2785" = 0.5; taper "d2786" = 0 deg
sketch "スケッチ147"
  geometry: L1 (7.75, -11.178)-(2.75, -11.178) reference; L2 (2.75, -11.178)-(2.75, -14.178) reference; L3 (2.75, -14.178)-(7.75, -14.178) reference; L4 (3.3, -11.678)-(3.9, -11.678); L5 (3.9, -11.678)-(3.9, -13.378); L6 (3.9, -13.378)-(3.3, -13.378); L7 (3.3, -13.378)-(3.3, -11.678); L8 (4.4, -11.678)-(5, -11.678); L9 (5, -11.678)-(5, -13.378); L10 (5, -13.378)-(4.4, -13.378); L11 (4.4, -13.378)-(4.4, -11.678); L12 (5.5, -11.678)-(6.1, -11.678); L13 (6.1, -11.678)-(6.1, -13.378); L14 (6.1, -13.378)-(5.5, -13.378); L15 (5.5, -13.378)-(5.5, -11.678); L16 (6.6, -11.678)-(7.2, -11.678); L17 (7.2, -11.678)-(7.2, -13.378); L18 (7.2, -13.378)-(6.6, -13.378); L19 (6.6, -13.378)-(6.6, -11.678); L20 (9.8, -11.678)-(10.4, -11.678); L21 (10.4, -11.678)-(10.4, -13.378); L22 (10.4, -13.378)-(9.8, -13.378); L23 (9.8, -13.378)-(9.8, -11.678); L24 (10.9, -11.678)-(11.5, -11.678); L25 (11.5, -11.678)-(11.5, -13.378); L26 (11.5, -13.378)-(10.9, -13.378); L27 (10.9, -13.378)-(10.9, -11.678); L28 (12, -11.678)-(12.6, -11.678); L29 (12.6, -11.678)-(12.6, -13.378); L30 (12.6, -13.378)-(12, -13.378); L31 (12, -13.378)-(12, -11.678); L32 (13.1, -11.678)-(13.7, -11.678); L33 (13.7, -11.678)-(13.7, -13.378); L34 (13.7, -13.378)-(13.1, -13.378); L35 (13.1, -13.378)-(13.1, -11.678); L36 (9.25, -11.178)-(9.25, -14.178) reference; L37 (16.3, -11.678)-(16.9, -11.678); L38 (16.9, -11.678)-(16.9, -13.378); L39 (16.9, -13.378)-(16.3, -13.378); L40 (16.3, -13.378)-(16.3, -11.678); L41 (17.4, -11.678)-(18, -11.678); L42 (18, -11.678)-(18, -13.378); L43 (18, -13.378)-(17.4, -13.378); L44 (17.4, -13.378)-(17.4, -11.678); L45 (18.5, -11.678)-(19.1, -11.678); L46 (19.1, -11.678)-(19.1, -13.378); L47 (19.1, -13.378)-(18.5, -13.378); L48 (18.5, -13.378)-(18.5, -11.678); L49 (19.6, -11.678)-(20.2, -11.678); L50 (20.2, -11.678)-(20.2, -13.378); L51 (20.2, -13.378)-(19.6, -13.378); L52 (19.6, -13.378)-(19.6, -11.678); L53 (15.75, -11.178)-(15.75, -14.178) reference; L54 (22.8, -11.678)-(23.4, -11.678); L55 (23.4, -11.678)-(23.4, -13.378); L56 (23.4, -13.378)-(22.8, -13.378); L57 (22.8, -13.378)-(22.8, -11.678); L58 (23.9, -11.678)-(24.5, -11.678); L59 (24.5, -11.678)-(24.5, -13.378); L60 (24.5, -13.378)-(23.9, -13.378); L61 (23.9, -13.378)-(23.9, -11.678); L62 (25, -11.678)-(25.6, -11.678); L63 (25.6, -11.678)-(25.6, -13.378); L64 (25.6, -13.378)-(25, -13.378)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; 1 further point
  constraints: 256 end point, 64 parallel, 32 horizontal, 32 perpendicular
  dimensions: "d2787" = 0.6 distance of L4.start L4.end; "d2789" = 0.5 distance between parallel lines of L11 L5; "d2790" = 0.5 distance between parallel lines of L15 L9; "d2791" = 0.5 distance between parallel lines of L19 L13; "d2792" = 0.6 distance of L8.start L8.end; "d2793" = 0.6 distance of L12.start L12.end; "d2794" = 0.6 distance of L16.start L16.end; "d2795" = 0.55 distance between parallel lines of L2 L7; "d2796" = 0.8 distance between parallel lines of L3 L6; "d2797" = 0 distance between parallel lines of L10 L6; "d2798" = 0 distance between parallel lines of L14 L10; "d2799" = 0 distance between parallel lines of L18 L14; "d2800" = 0.5 distance between parallel lines of L4 L1; "d2801" = 0.6 distance of L20.start L20.end; "d2802" = 0.5 distance between parallel lines of L21 L27; "d2803" = 0.5 distance between parallel lines of L25 L31; "d2804" = 0.5 distance between parallel lines of L35 L29; "d2805" = 0.6 distance of L24.start L24.end; "d2806" = 0.6 distance of L28.start L28.end; "d2807" = 0.6 distance of L32.start L32.end; "d2808" = 0.55 distance between parallel lines of L36 L23; "d2809" = 0.55 distance between parallel lines of L53 L40; "d2810" = 0.5 distance between parallel lines of L38 L44; "d2811" = 0.5 distance between parallel lines of L48 L42; "d2812" = 0.5 distance between parallel lines of L52 L46; "d2813" = 0.6 distance of L37.start L37.end; "d2814" = 0.6 distance of L41.start L41.end; "d2815" = 0.6 distance of L45.start L45.end; "d2816" = 0.6 distance of L49.start L49.end; "d2817" = 0.55 distance between parallel lines of L70 L57; "d2818" = 0.5 distance between parallel lines of L61 L55; "d2819" = 0.5 distance between parallel lines of L65 L59; "d2820" = 0.5 distance between parallel lines of L69 L63; "d2821" = 0.6 distance of L54.start L54.end; "d2822" = 0.6 distance of L58.start L58.end; "d2823" = 0.6 distance of L62.start L62.end; "d2824" = 0.6 distance of L66.start L66.end; "d2825" = 0.5 distance between parallel lines of L87 L71; "d2826" = 0.8 distance between parallel lines of L88 L73; "d2827" = 0 distance between parallel lines of L77 L73; "d2828" = 0 distance between parallel lines of L81 L73; "d2829" = 0 distance between parallel lines of L85 L81; "d2830" = 0 distance between parallel lines of L71 L75; "d2831" = 0 distance between parallel lines of L79 L75; "d2832" = 0 distance between parallel lines of L83 L79
extrude "押し出し137" cut sketch "スケッチ147" distance "d2833" = 0.5; taper "d2834" = 0 deg
sketch "スケッチ148"
  geometry: L1 (8.75, -10.9)-(3.75, -10.9) reference; L2 (3.75, -10.9)-(3.75, -13.9) reference; L3 (3.75, -13.9)-(8.75, -13.9) reference; L4 (4.3, -11.4)-(4.9, -11.4); L5 (4.9, -11.4)-(4.9, -13.1); L6 (4.9, -13.1)-(4.3, -13.1); L7 (4.3, -13.1)-(4.3, -11.4); L8 (5.4, -11.4)-(6, -11.4); L9 (6, -11.4)-(6, -13.1); L10 (6, -13.1)-(5.4, -13.1); L11 (5.4, -13.1)-(5.4, -11.4); L12 (6.5, -11.4)-(7.1, -11.4); L13 (7.1, -11.4)-(7.1, -13.1); L14 (7.1, -13.1)-(6.5, -13.1); L15 (6.5, -13.1)-(6.5, -11.4); L16 (7.6, -11.4)-(8.2, -11.4); L17 (8.2, -11.4)-(8.2, -13.1); L18 (8.2, -13.1)-(7.6, -13.1); L19 (7.6, -13.1)-(7.6, -11.4); L20 (10.8, -11.4)-(11.4, -11.4); L21 (11.4, -11.4)-(11.4, -13.1); L22 (11.4, -13.1)-(10.8, -13.1); L23 (10.8, -13.1)-(10.8, -11.4); L24 (11.9, -11.4)-(12.5, -11.4); L25 (12.5, -11.4)-(12.5, -13.1); L26 (12.5, -13.1)-(11.9, -13.1); L27 (11.9, -13.1)-(11.9, -11.4); L28 (13, -11.4)-(13.6, -11.4); L29 (13.6, -11.4)-(13.6, -13.1); L30 (13.6, -13.1)-(13, -13.1); L31 (13, -13.1)-(13, -11.4); L32 (14.1, -11.4)-(14.7, -11.4); L33 (14.7, -11.4)-(14.7, -13.1); L34 (14.7, -13.1)-(14.1, -13.1); L35 (14.1, -13.1)-(14.1, -11.4); L36 (10.25, -10.9)-(10.25, -13.9) reference; L37 (17.3, -11.4)-(17.9, -11.4); L38 (17.9, -11.4)-(17.9, -13.1); L39 (17.9, -13.1)-(17.3, -13.1); L40 (17.3, -13.1)-(17.3, -11.4); L41 (18.4, -11.4)-(19, -11.4); L42 (19, -11.4)-(19, -13.1); L43 (19, -13.1)-(18.4, -13.1); L44 (18.4, -13.1)-(18.4, -11.4); L45 (19.5, -11.4)-(20.1, -11.4); L46 (20.1, -11.4)-(20.1, -13.1); L47 (20.1, -13.1)-(19.5, -13.1); L48 (19.5, -13.1)-(19.5, -11.4); L49 (20.6, -11.4)-(21.2, -11.4); L50 (21.2, -11.4)-(21.2, -13.1); L51 (21.2, -13.1)-(20.6, -13.1); L52 (20.6, -13.1)-(20.6, -11.4); L53 (16.75, -10.9)-(16.75, -13.9) reference; L54 (23.8, -11.4)-(24.4, -11.4); L55 (24.4, -11.4)-(24.4, -13.1); L56 (24.4, -13.1)-(23.8, -13.1); L57 (23.8, -13.1)-(23.8, -11.4); L58 (24.9, -11.4)-(25.5, -11.4); L59 (25.5, -11.4)-(25.5, -13.1); L60 (25.5, -13.1)-(24.9, -13.1); L61 (24.9, -13.1)-(24.9, -11.4); L62 (26, -11.4)-(26.6, -11.4); L63 (26.6, -11.4)-(26.6, -13.1); L64 (26.6, -13.1)-(26, -13.1)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; 1 further point
  constraints: 256 end point, 64 parallel, 32 horizontal, 32 perpendicular
  dimensions: "d2835" = 0.55 distance between parallel lines of L2 L7; "d2836" = 0.5 distance between parallel lines of L11 L5; "d2837" = 0.5 distance between parallel lines of L15 L9; "d2838" = 0.5 distance between parallel lines of L19 L13; "d2839" = 0.6 distance of L4.start L4.end; "d2840" = 0.6 distance of L8.start L8.end; "d2841" = 0.6 distance of L12.start L12.end; "d2842" = 0.6 distance of L16.start L16.end; "d2843" = 0.5 distance between parallel lines of L4 L1; "d2844" = 0.8 distance between parallel lines of L3 L6; "d2845" = 0 distance between parallel lines of L10 L6; "d2846" = 0 distance between parallel lines of L14 L10; "d2847" = 0 distance between parallel lines of L18 L14; "d2848" = 0.55 distance between parallel lines of L23 L36; "d2849" = 0.5 distance between parallel lines of L27 L21; "d2850" = 0.5 distance between parallel lines of L31 L25; "d2851" = 0.5 distance between parallel lines of L35 L29; "d2852" = 0.6 distance of L20.start L20.end; "d2853" = 0.6 distance of L24.start L24.end; "d2854" = 0.6 distance of L28.start L28.end; "d2855" = 0.6 distance of L32.start L32.end; "d2856" = 0.55 distance between parallel lines of L53 L40; "d2857" = 0.5 distance between parallel lines of L44 L38; "d2858" = 0.5 distance between parallel lines of L48 L42; "d2859" = 0.5 distance between parallel lines of L52 L46; "d2860" = 0.6 distance of L37.start L37.end; "d2861" = 0.6 distance of L41.start L41.end; "d2862" = 0.6 distance of L45.start L45.end; "d2863" = 0.6 distance of L49.start L49.end; "d2864" = 0.55 distance between parallel lines of L70 L57; "d2865" = 0.5 distance between parallel lines of L61 L55; "d2866" = 0.5 distance between parallel lines of L65 L59; "d2867" = 0.5 distance between parallel lines of L69 L63; "d2868" = 0.6 distance of L54.start L54.end; "d2869" = 0.6 distance of L58.start L58.end; "d2870" = 0.6 distance of L62.start L62.end; "d2871" = 0.6 distance of L66.start L66.end; "d2872" = 0.5 distance between parallel lines of L87 L71; "d2873" = 0.8 distance between parallel lines of L88 L73; "d2874" = 0 distance between parallel lines of L77 L73; "d2875" = 0 distance between parallel lines of L81 L77; "d2876" = 0 distance between parallel lines of L85 L81; "d2877" = 0 distance between parallel lines of L75 L71; "d2878" = 0 distance between parallel lines of L79 L75; "d2879" = 0 distance between parallel lines of L83 L79
extrude "押し出し138" cut sketch "スケッチ148" distance "d2880" = 0.5; taper "d2881" = 0 deg
sketch "スケッチ149"
  geometry: L1 (8.5, -10.882)-(3.5, -10.882) reference; L2 (3.5, -10.882)-(3.5, -13.882) reference; L3 (3.5, -13.882)-(8.5, -13.882) reference; L4 (4.05, -11.382)-(4.65, -11.382); L5 (4.65, -11.382)-(4.65, -13.082); L6 (4.65, -13.082)-(4.05, -13.082); L7 (4.05, -13.082)-(4.05, -11.382); L8 (5.15, -11.382)-(5.75, -11.382); L9 (5.75, -11.382)-(5.75, -13.082); L10 (5.75, -13.082)-(5.15, -13.082); L11 (5.15, -13.082)-(5.15, -11.382); L12 (6.25, -11.382)-(6.85, -11.382); L13 (6.85, -11.382)-(6.85, -13.082); L14 (6.85, -13.082)-(6.25, -13.082); L15 (6.25, -13.082)-(6.25, -11.382); L16 (7.35, -11.382)-(7.95, -11.382); L17 (7.95, -11.382)-(7.95, -13.082); L18 (7.95, -13.082)-(7.35, -13.082); L19 (7.35, -13.082)-(7.35, -11.382); L20 (10.55, -11.382)-(11.15, -11.382); L21 (11.15, -11.382)-(11.15, -13.082); L22 (11.15, -13.082)-(10.55, -13.082); L23 (10.55, -13.082)-(10.55, -11.382); L24 (11.65, -11.382)-(12.25, -11.382); L25 (12.25, -11.382)-(12.25, -13.082); L26 (12.25, -13.082)-(11.65, -13.082); L27 (11.65, -13.082)-(11.65, -11.382); L28 (12.75, -11.382)-(13.35, -11.382); L29 (13.35, -11.382)-(13.35, -13.082); L30 (13.35, -13.082)-(12.75, -13.082); L31 (12.75, -13.082)-(12.75, -11.382); L32 (13.85, -11.382)-(14.45, -11.382); L33 (14.45, -11.382)-(14.45, -13.082); L34 (14.45, -13.082)-(13.85, -13.082); L35 (13.85, -13.082)-(13.85, -11.382); L36 (10, -10.961)-(10, -13.882) reference; L37 (17.05, -11.382)-(17.65, -11.382); L38 (17.65, -11.382)-(17.65, -13.082); L39 (17.65, -13.082)-(17.05, -13.082); L40 (17.05, -13.082)-(17.05, -11.382); L41 (18.15, -11.382)-(18.75, -11.382); L42 (18.75, -11.382)-(18.75, -13.082); L43 (18.75, -13.082)-(18.15, -13.082); L44 (18.15, -13.082)-(18.15, -11.382); L45 (19.25, -11.382)-(19.85, -11.382); L46 (19.85, -11.382)-(19.85, -13.082); L47 (19.85, -13.082)-(19.25, -13.082); L48 (19.25, -13.082)-(19.25, -11.382); L49 (20.35, -11.382)-(20.95, -11.382); L50 (20.95, -11.382)-(20.95, -13.082); L51 (20.95, -13.082)-(20.35, -13.082); L52 (20.35, -13.082)-(20.35, -11.382); L53 (16.5, -10.961)-(16.5, -13.882) reference; L54 (4.05, -29)-(4.65, -29); L55 (4.65, -29)-(4.65, -30.7); L56 (4.65, -30.7)-(4.05, -30.7); L57 (4.05, -30.7)-(4.05, -29); L58 (5.15, -29)-(5.75, -29); L59 (5.75, -29)-(5.75, -30.7); L60 (5.75, -30.7)-(5.15, -30.7); L61 (5.15, -30.7)-(5.15, -29); L62 (6.25, -29)-(6.85, -29); L63 (6.85, -29)-(6.85, -30.7); L64 (6.85, -30.7)-(6.25, -30.7)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; 1 further point
  constraints: 192 end point, 48 parallel, 24 horizontal, 24 perpendicular
  dimensions: "d2882" = 0.55 distance between parallel lines of L2 L7; "d2883" = 0.5 distance between parallel lines of L11 L5; "d2884" = 0.5 distance between parallel lines of L15 L9; "d2885" = 0.5 distance between parallel lines of L19 L13; "d2886" = 0.6 distance of L4.start L4.end; "d2887" = 0.6 distance of L8.start L8.end; "d2888" = 0.6 distance of L12.start L12.end; "d2889" = 0.6 distance of L16.start L16.end; "d2890" = 0.5 distance between parallel lines of L4 L1; "d2891" = 0.8 distance between parallel lines of L3 L6; "d2892" = 0 distance between parallel lines of L10 L6; "d2893" = 0 distance between parallel lines of L14 L10; "d2894" = 0 distance between parallel lines of L18 L14; "d2895" = 0.55 distance between parallel lines of L23 L36; "d2896" = 0.5 distance between parallel lines of L27 L21; "d2897" = 0.5 distance between parallel lines of L31 L25; "d2898" = 0.5 distance between parallel lines of L35 L29; "d2899" = 0.6 distance of L20.start L20.end; "d2900" = 0.6 distance of L24.start L24.end; "d2901" = 0.6 distance of L28.start L28.end; "d2902" = 0.6 distance of L32.start L32.end; "d2903" = 0.55 distance between parallel lines of L53 L40; "d2904" = 0.5 distance between parallel lines of L44 L38; "d2905" = 0.5 distance between parallel lines of L48 L42; "d2906" = 0.5 distance between parallel lines of L52 L46; "d2907" = 0.6 distance of L37.start L37.end; "d2908" = 0.6 distance of L41.start L41.end; "d2909" = 0.6 distance of L45.start L45.end; "d2910" = 0.6 distance of L49.start L49.end; "d2911" = 0.5 distance between parallel lines of L70 L54; "d2912" = 0.8 distance between parallel lines of L71 L56; "d2913" = 0 distance between parallel lines of L58 L54; "d2914" = 0 distance between parallel lines of L62 L58; "d2915" = 0 distance between parallel lines of L66 L62; "d2916" = 0 distance between parallel lines of L60 L56; "d2917" = 0 distance between parallel lines of L64 L60; "d2918" = 0 distance between parallel lines of L68 L64
extrude "押し出し139" cut sketch "スケッチ149" distance "d2919" = 0.5; taper "d2920" = 0 deg
sketch "スケッチ150"
  geometry: L1 (8.25, 23.036)-(3.25, 23.036) reference; L2 (3.25, 23.036)-(3.25, 20.036) reference; L3 (3.25, 20.036)-(8.25, 20.036) reference; L4 (3.8, 22.536)-(4.4, 22.536); L5 (4.4, 22.536)-(4.4, 20.836); L6 (4.4, 20.836)-(3.8, 20.836); L7 (3.8, 20.836)-(3.8, 22.536); L8 (4.9, 22.536)-(5.5, 22.536); L9 (5.5, 22.536)-(5.5, 20.836); L10 (5.5, 20.836)-(4.9, 20.836); L11 (4.9, 20.836)-(4.9, 22.536); L12 (6, 22.536)-(6.6, 22.536); L13 (6.6, 22.536)-(6.6, 20.836); L14 (6.6, 20.836)-(6, 20.836); L15 (6, 20.836)-(6, 22.536); L16 (7.1, 22.536)-(7.7, 22.536); L17 (7.7, 22.536)-(7.7, 20.836); L18 (7.7, 20.836)-(7.1, 20.836); L19 (7.1, 20.836)-(7.1, 22.536); L20 (10.8, 22.536)-(11.4, 22.536); L21 (11.4, 22.536)-(11.4, 20.836); L22 (11.4, 20.836)-(10.8, 20.836); L23 (10.8, 20.836)-(10.8, 22.536); L24 (11.9, 22.536)-(12.5, 22.536); L25 (12.5, 22.536)-(12.5, 20.836); L26 (12.5, 20.836)-(11.9, 20.836); L27 (11.9, 20.836)-(11.9, 22.536); L28 (13, 22.536)-(13.6, 22.536); L29 (13.6, 22.536)-(13.6, 20.836); L30 (13.6, 20.836)-(13, 20.836); L31 (13, 20.836)-(13, 22.536); L32 (14.1, 22.536)-(14.7, 22.536); L33 (14.7, 22.536)-(14.7, 20.836); L34 (14.7, 20.836)-(14.1, 20.836); L35 (14.1, 20.836)-(14.1, 22.536); L36 (10.25, 23.036)-(10.25, 20.036) reference; L37 (37.24, 22.536)-(37.84, 22.536); L38 (37.84, 22.536)-(37.84, 20.836); L39 (37.84, 20.836)-(37.24, 20.836); L40 (37.24, 20.836)-(37.24, 22.536); L41 (38.34, 22.536)-(38.94, 22.536); L42 (38.94, 22.536)-(38.94, 20.836); L43 (38.94, 20.836)-(38.34, 20.836); L44 (38.34, 20.836)-(38.34, 22.536); L45 (39.44, 22.536)-(40.04, 22.536); L46 (40.04, 22.536)-(40.04, 20.836); L47 (40.04, 20.836)-(39.44, 20.836); L48 (39.44, 20.836)-(39.44, 22.536); L49 (40.54, 22.536)-(41.14, 22.536); L50 (41.14, 22.536)-(41.14, 20.836); L51 (41.14, 20.836)-(40.54, 20.836); L52 (40.54, 20.836)-(40.54, 22.536); L53 (36.69, 23.036)-(36.69, 20.036) reference; L54 (44.24, 22.536)-(44.84, 22.536); L55 (44.84, 22.536)-(44.84, 20.836); L56 (44.84, 20.836)-(44.24, 20.836); L57 (44.24, 20.836)-(44.24, 22.536); L58 (45.34, 22.536)-(45.94, 22.536); L59 (45.94, 22.536)-(45.94, 20.836); L60 (45.94, 20.836)-(45.34, 20.836); L61 (45.34, 20.836)-(45.34, 22.536); L62 (46.44, 22.536)-(47.04, 22.536); L63 (47.04, 22.536)-(47.04, 20.836); L64 (47.04, 20.836)-(46.44, 20.836)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; 1 further point
  constraints: 256 end point, 64 parallel, 32 horizontal, 32 perpendicular
  dimensions: "d2921" = 0.55 distance between parallel lines of L2 L7; "d2922" = 0.5 distance between parallel lines of L11 L5; "d2923" = 0.5 distance between parallel lines of L15 L9; "d2924" = 0.5 distance between parallel lines of L19 L13; "d2925" = 0.6 distance of L4.start L4.end; "d2926" = 0.6 distance of L8.start L8.end; "d2927" = 0.6 distance of L12.start L12.end; "d2928" = 0.6 distance of L16.start L16.end; "d2929" = 0.5 distance between parallel lines of L4 L1; "d2930" = 0.8 distance between parallel lines of L3 L6; "d2931" = 0 distance between parallel lines of L10 L6; "d2932" = 0 distance between parallel lines of L14 L10; "d2933" = 0 distance between parallel lines of L18 L14; "d2934" = 0.55 distance between parallel lines of L23 L36; "d2935" = 0.5 distance between parallel lines of L27 L21; "d2936" = 0.5 distance between parallel lines of L31 L25; "d2937" = 0.5 distance between parallel lines of L35 L29; "d2938" = 0.6 distance of L20.start L20.end; "d2939" = 0.6 distance of L24.start L24.end; "d2940" = 0.6 distance of L28.start L28.end; "d2941" = 0.6 distance of L32.start L32.end; "d2942" = 0.55 distance between parallel lines of L53 L40; "d2943" = 0.5 distance between parallel lines of L44 L38; "d2944" = 0.5 distance between parallel lines of L48 L42; "d2945" = 0.5 distance between parallel lines of L46 L52; "d2946" = 0.6 distance of L37.start L37.end; "d2947" = 0.6 distance of L41.start L41.end; "d2948" = 0.6 distance of L45.start L45.end; "d2949" = 0.6 distance of L49.start L49.end; "d2950" = 0.55 distance between parallel lines of L57 L70; "d2951" = 0.5 distance between parallel lines of L61 L55; "d2952" = 0.5 distance between parallel lines of L65 L59; "d2953" = 0.5 distance between parallel lines of L69 L63; "d2954" = 0.6 distance of L54.start L54.end; "d2955" = 0.6 distance of L58.start L58.end; "d2956" = 0.6 distance of L62.start L62.end; "d2957" = 0.6 distance of L66.start L66.end; "d2958" = 0.5 distance between parallel lines of L71 L87; "d2959" = 0 distance between parallel lines of L75 L71; "d2960" = 0 distance between parallel lines of L79 L75; "d2961" = 0 distance between parallel lines of L83 L79; "d2962" = 0.8 distance between parallel lines of L88 L73; "d2963" = 0 distance between parallel lines of L73 L77; "d2964" = 0 distance between parallel lines of L81 L77; "d2965" = 0 distance between parallel lines of L85 L81
extrude "押し出し140" cut sketch "スケッチ150" distance "d2966" = 0.5; taper "d2967" = 0 deg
